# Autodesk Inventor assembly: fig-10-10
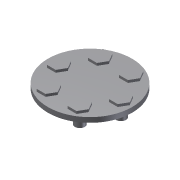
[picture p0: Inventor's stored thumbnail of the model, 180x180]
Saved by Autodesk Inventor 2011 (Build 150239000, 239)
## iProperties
Created: 2008-05
Part Number: fig-10-10
Document SubType Name: Assembly
Designer: CADCIM
Author: CADCIM
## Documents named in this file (3)
- C:\Users\CADSoft\Desktop\part files\c10-inv-2011-prt\fig-10-10.iam
- C:\Users\CADSoft\Desktop\inventor\c10-inv-2010-prt\c10\Part4.ipt
- C:\Users\CADSoft\Desktop\inventor\c10-inv-2010-prt\c10\Part5.ipt
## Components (7 placed, 2 different names)
1. Part4:1
2. Part5:1
3. Part5:2
4. Part5:3
5. Part5:4
6. Part5:5
7. Part5:6
